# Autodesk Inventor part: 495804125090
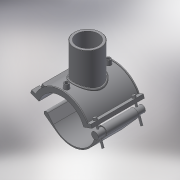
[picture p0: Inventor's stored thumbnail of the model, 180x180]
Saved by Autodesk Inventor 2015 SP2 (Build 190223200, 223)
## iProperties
Created: 2017-07
Part Number: 495804125090
Material: Generic
Description: PLASSON BRANCH SADDLE 125-90
Document SubType Name: Modeling
Designer: KIM
Density: 1 g/cm^3
Appearance: Default
Author: KIM
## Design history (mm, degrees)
derived "495804.ipt"
feature "Solid1::495804.ipt"
feature "Solid2::495804.ipt"
tag "TaggingFeature1"
body "Solid1"
body "Solid2"
other parameters: "d0" = 125, "d2" = 169, "d3" = 31.25, "d4" = 176, "d5" = 0, "d6" = 0.1, "d8" = 0, "d19" = 6, "d20" = 6, "d21" = 105.6, "d23" = 0, "d24" = 52.8, "d26" = 0, "d27" = 3, "d28" = 3, "d29" = 3, "d30" = 41.66667, "d31" = 6, "d32" = 0, "d33" = 0, "d34" = 0.6, "d40" = 80.6, "d41" = 99, "d43" = 0, "d45" = 0, "d47" = 182.5, "d50" = 0, "d70" = 15, "d72" = 0, "d73" = 6, "d75" = 5, "d76" = 0, "d77" = 6.25, "d78" = 92.5, "d79" = 15, "d80" = 70.4, "d82" = 5 deg, "d84" = 4, "d85" = 14, "d86" = 0, "d87" = 3, "d88" = 0, "d89" = 1, "d90" = 1, "d91" = 140.8, "d92" = 0, "d93" = 0.5, "d94" = 65.78947, "d96" = 158.1, "d97" = 3.52, "d98" = 0, "d102" = 2.7, "d103" = 72, "d105" = 0, "d109" = -35, "d117" = 0.9, "d120" = 140 deg, "d121" = 24.228, "d122" = 20 deg, "d124" = 93, "d126" = 0, "d143" = 131.25, "d150" = 22.5, "d159" = 6, "d161" = 3.125, "d162" = 105.6, "d163" = 0, "d167" = 25, "d168" = 70.45455, "d173" = 1, "d175" = 62.5, "d176" = 20 deg, "d177" = 8.75, "d178" = 27, "d180" = 0, "d185" = 57.2, "d186" = 57.2, "d187" = 77.5, "d188" = 9, "d189" = 8.75, "d190" = 0, "d191" = 116.25, "d200" = 15, "d202" = 0, "d216" = 158.4, "d217" = 0, "d221" = 65.12, "d222" = 8.75, "d223" = 5.25, "d224" = 62.5, "d225" = 5.25, "d227" = 18, "d230" = 83.75, "d236" = 20 deg, "d237" = 83.5, "d238" = 20 deg, "d239" = 8.75, "d_" = 125, "B_" = 169, "H_" = 105, "L_" = 176, "d_t" = 6, "d1" = 155, "d148" = 3.125, "d160" = 3.125
